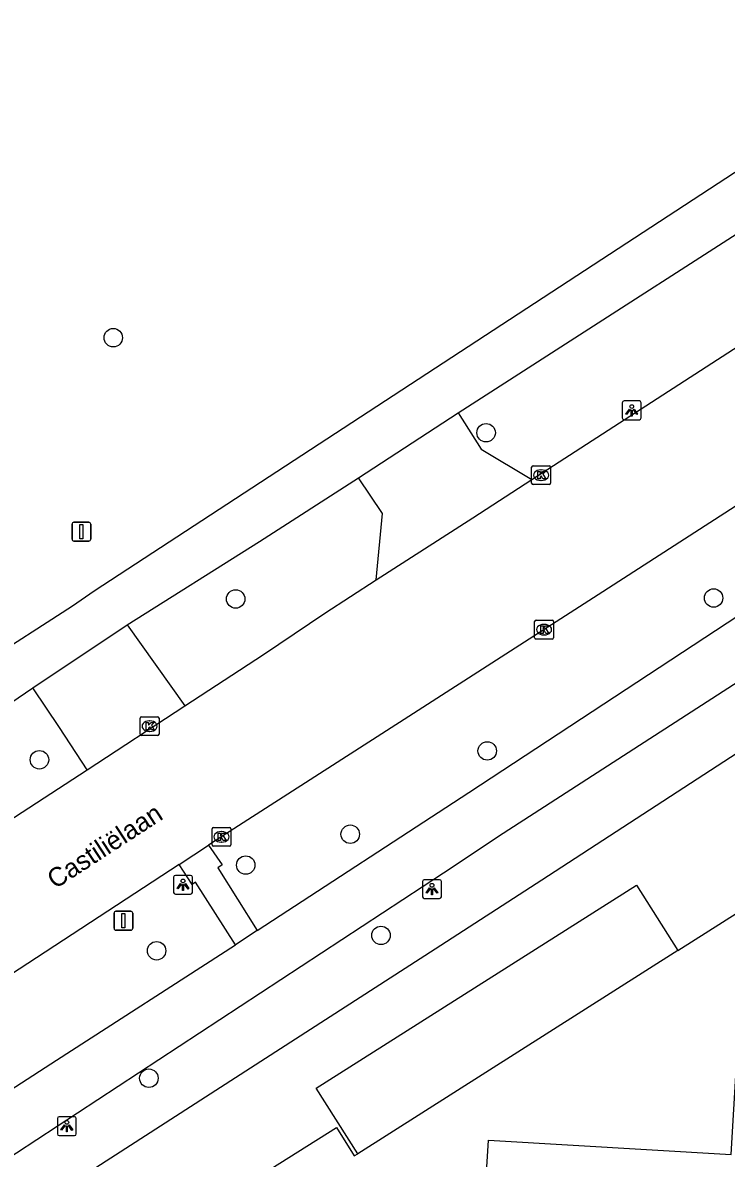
# Model space of a CAD drawing. Extents: x 159451 to 160663, y 388402 to 389723.
# Drawn here: x 159714 to 159751.3, y 389147.8 to 389208 of the extents above; entities that cross this region are included whole.
import ezdxf

# ---------------------------------------------------------------- set-up
doc = ezdxf.new("R2010")
doc.units = 0
for name, color, linetype in [('IMGEO_Boom', 7, 'Continuous'), ('IMGEO_Erf', 7, 'Continuous'), ('IMGEO_Fietspad_gesloten', 7, 'Continuous'), ('IMGEO_Kolk', 7, 'Continuous'), ('IMGEO_Lichtpunt', 7, 'Continuous'), ('IMGEO_Openbare_ruimte_label', 7, 'Continuous'), ('IMGEO_Pand', 7, 'Continuous'), ('IMGEO_Rijbaan_lokaal_gesloten', 7, 'Continuous'), ('IMGEO_Rijbaan_lokaal_open', 7, 'Continuous'), ('IMGEO_Verkeersbordpaal', 7, 'Continuous'), ('IMGEO_Voetpad_open', 7, 'Continuous')]:
    doc.layers.add(name, color=color, linetype=linetype)

msp = doc.modelspace()

# ---------------------------------------------------------------- linework, layer by layer
at = {"layer": 'IMGEO_Boom'}
for centre in [(159718.826, 389191.343), (159738.577, 389186.302), (159725.311, 389177.491), (159750.626, 389177.542), (159738.634, 389169.436), (159714.918, 389168.964), (159731.379, 389165.02), (159725.845, 389163.382), (159733.007, 389159.655), (159721.121, 389158.839), (159720.712, 389152.084)]:
    msp.add_circle(centre, 0.489, dxfattribs=at)
at = {"layer": 'IMGEO_Erf'}
for points in [[(159748.739, 389158.847), (159759.109, 389165.438), (159760.359, 389163.401)], [(159722.516, 389095.413), (159722.792, 389100.259), (159711.104, 389100.923), (159702.284, 389112.933), (159706.835, 389116.275), (159698.631, 389129.303), (159730.65, 389149.467), (159731.596, 389147.964), (159731.782, 389148.082)]]:
    msp.add_lwpolyline(points, dxfattribs=at)
at = {"layer": 'IMGEO_Fietspad_gesloten'}
for points in [[(159696.145, 389164.01), (159699.251, 389166.039), (159708.794, 389172.235), (159708.905, 389172.147), (159709.019, 389172.233), (159711.829, 389174.024), (159716.666, 389177.127), (159717.814, 389177.926), (159784.328, 389221.435)], [(159737.096, 389187.355), (159758.299, 389200.996), (159781.643, 389216.263)], [(159726.442, 389159.917), (159737.666, 389167.226), (159753.709, 389177.779), (159791.193, 389202.242)], [(159689.337, 389132.758), (159694.349, 389135.637), (159709.37, 389145.295), (159736.324, 389162.971), (159739.475, 389165.082), (159753.328, 389174.015), (159770.977, 389185.573), (159792.742, 389199.315)], [(159719.558, 389176.127), (159726.565, 389180.529), (159731.823, 389183.917)], [(159677.543, 389148.933), (159683.696, 389152.464), (159687.097, 389154.672), (159691.96, 389158.015), (159702.684, 389165.018), (159709.597, 389169.401), (159714.574, 389172.778)], [(159726.442, 389159.917), (159725.301, 389159.156)], [(159686.936, 389134.846), (159692.451, 389138.046), (159696.672, 389140.641), (159715.829, 389153.048), (159725.301, 389159.156)]]:
    msp.add_lwpolyline(points, dxfattribs=at)
at = {"layer": 'IMGEO_Kolk'}
for p, q in [((159740.988, 389183.631), (159740.988, 389184.483)), ((159741.063, 389184.557), (159741.915, 389184.557)), ((159741.476, 389184.337), (159741.501, 389184.337)), ((159741.989, 389184.483), (159741.989, 389183.631)), ((159741.499, 389183.777), (159741.474, 389183.777)), ((159741.915, 389183.557), (159741.063, 389183.557)), ((159741.146, 389175.439), (159741.146, 389176.291)), ((159741.221, 389176.365), (159742.073, 389176.365)), ((159741.634, 389176.145), (159741.659, 389176.145)), ((159742.147, 389176.291), (159742.147, 389175.439)), ((159742.073, 389175.365), (159741.221, 389175.365)), ((159741.657, 389175.585), (159741.632, 389175.585)), ((159720.253, 389170.323), (159720.253, 389171.175)), ((159720.328, 389171.249), (159721.18, 389171.249)), ((159720.741, 389171.029), (159720.766, 389171.029)), ((159721.254, 389171.175), (159721.254, 389170.323)), ((159720.764, 389170.469), (159720.739, 389170.469)), ((159721.18, 389170.249), (159720.328, 389170.249)), ((159724.061, 389164.451), (159724.061, 389165.303)), ((159724.136, 389165.377), (159724.988, 389165.377)), ((159724.549, 389165.157), (159724.574, 389165.157)), ((159725.062, 389165.303), (159725.062, 389164.451)), ((159724.988, 389164.377), (159724.136, 389164.377)), ((159724.572, 389164.597), (159724.547, 389164.597))]:
    msp.add_line(p, q, dxfattribs=at)
for points in [[(159740.988, 389183.631), (159740.988, 389184.483)], [(159741.063, 389184.557), (159741.915, 389184.557)], [(159741.309, 389184.257), (159741.432, 389184.257), (159741.432, 389184.106), (159741.562, 389184.257), (159741.726, 389184.257), (159741.58, 389184.106), (159741.733, 389183.857), (159741.581, 389183.857), (159741.496, 389184.021), (159741.432, 389183.954), (159741.432, 389183.857), (159741.309, 389183.857), (159741.309, 389184.257)], [(159741.989, 389184.483), (159741.989, 389183.631)], [(159741.915, 389183.557), (159741.063, 389183.557)], [(159741.146, 389175.439), (159741.146, 389176.291)], [(159741.221, 389176.365), (159742.073, 389176.365)], [(159741.467, 389176.065), (159741.59, 389176.065), (159741.59, 389175.914), (159741.72, 389176.065), (159741.884, 389176.065), (159741.738, 389175.914), (159741.891, 389175.665), (159741.739, 389175.665), (159741.654, 389175.829), (159741.59, 389175.762), (159741.59, 389175.665), (159741.467, 389175.665), (159741.467, 389176.065)], [(159742.147, 389176.291), (159742.147, 389175.439)], [(159742.073, 389175.365), (159741.221, 389175.365)], [(159720.253, 389170.323), (159720.253, 389171.175)], [(159720.328, 389171.249), (159721.18, 389171.249)], [(159721.254, 389171.175), (159721.254, 389170.323)], [(159720.574, 389170.949), (159720.697, 389170.949), (159720.697, 389170.798), (159720.827, 389170.949), (159720.991, 389170.949), (159720.845, 389170.798), (159720.998, 389170.549), (159720.846, 389170.549), (159720.761, 389170.713), (159720.697, 389170.646), (159720.697, 389170.549), (159720.574, 389170.549), (159720.574, 389170.949)], [(159721.18, 389170.249), (159720.328, 389170.249)], [(159724.061, 389164.451), (159724.061, 389165.303)], [(159724.136, 389165.377), (159724.988, 389165.377)], [(159724.382, 389165.077), (159724.505, 389165.077), (159724.505, 389164.926), (159724.635, 389165.077), (159724.799, 389165.077), (159724.653, 389164.926), (159724.806, 389164.677), (159724.654, 389164.677), (159724.569, 389164.841), (159724.505, 389164.774), (159724.505, 389164.677), (159724.382, 389164.677), (159724.382, 389165.077)], [(159725.062, 389165.303), (159725.062, 389164.451)], [(159724.988, 389164.377), (159724.136, 389164.377)]]:
    msp.add_lwpolyline(points, dxfattribs=at)
for centre, start, end in [((159741.065, 389184.481), 91.55205, 178.44795), ((159741.065, 389184.481), 91.55205, 178.44795), ((159741.913, 389184.481), 1.55205, 88.44795), ((159741.913, 389184.481), 1.55205, 88.44795), ((159741.065, 389183.633), 181.55205, 268.44795), ((159741.065, 389183.633), 181.55205, 268.44795), ((159741.913, 389183.633), 271.55205, 358.44795), ((159741.913, 389183.633), 271.55205, 358.44795), ((159741.223, 389176.289), 91.55205, 178.44795), ((159741.223, 389176.289), 91.55205, 178.44795), ((159742.071, 389176.289), 1.55205, 88.44795), ((159742.071, 389176.289), 1.55205, 88.44795), ((159741.223, 389175.441), 181.55205, 268.44795), ((159741.223, 389175.441), 181.55205, 268.44795), ((159742.071, 389175.441), 271.55205, 358.44795), ((159742.071, 389175.441), 271.55205, 358.44795), ((159720.33, 389171.173), 91.55205, 178.44795), ((159720.33, 389171.173), 91.55205, 178.44795), ((159721.178, 389171.173), 1.55205, 88.44795), ((159721.178, 389171.173), 1.55205, 88.44795), ((159720.33, 389170.325), 181.55205, 268.44795), ((159720.33, 389170.325), 181.55205, 268.44795), ((159721.178, 389170.325), 271.55205, 358.44795), ((159721.178, 389170.325), 271.55205, 358.44795), ((159724.138, 389165.301), 91.55205, 178.44795), ((159724.138, 389165.301), 91.55205, 178.44795), ((159724.986, 389165.301), 1.55205, 88.44795), ((159724.986, 389165.301), 1.55205, 88.44795), ((159724.138, 389164.453), 181.55205, 268.44795), ((159724.138, 389164.453), 181.55205, 268.44795), ((159724.986, 389164.453), 271.55205, 358.44795), ((159724.986, 389164.453), 271.55205, 358.44795)]:
    msp.add_arc(centre, 0.0765, start, end, dxfattribs=at)
for centre, major_axis, ratio, start_param, end_param in [((159741.475, 389184.057), (-0.387, 0.002), 0.722429, 4.712389, 7.853982), ((159741.5, 389184.057), (-0.39, 0.002), 0.717154, 1.570796, 4.712389), ((159741.633, 389175.865), (-0.387, 0.002), 0.722429, 4.712389, 7.853982), ((159741.658, 389175.865), (-0.39, 0.002), 0.717154, 1.570796, 4.712389), ((159720.74, 389170.749), (-0.387, 0.002), 0.722429, 4.712389, 7.853982), ((159720.765, 389170.749), (-0.39, 0.002), 0.717154, 1.570796, 4.712389), ((159724.548, 389164.877), (-0.387, 0.002), 0.722429, 4.712389, 7.853982), ((159724.573, 389164.877), (-0.39, 0.002), 0.717154, 1.570796, 4.712389)]:
    msp.add_ellipse(centre, major_axis=major_axis, ratio=ratio, start_param=start_param, end_param=end_param, dxfattribs=at)
at = {"layer": 'IMGEO_Lichtpunt'}
for p, q in [((159745.791, 389187.893), (159745.791, 389187.086)), ((159745.791, 389187.893), (159745.791, 389187.086)), ((159746.693, 389187.988), (159745.885, 389187.988)), ((159746.693, 389187.988), (159745.885, 389187.988)), ((159746.787, 389187.086), (159746.787, 389187.893)), ((159746.787, 389187.086), (159746.787, 389187.893)), ((159745.885, 389186.992), (159746.693, 389186.992)), ((159745.885, 389186.992), (159746.693, 389186.992)), ((159722.022, 389162.741), (159722.022, 389161.934)), ((159722.022, 389162.741), (159722.022, 389161.934)), ((159722.924, 389162.836), (159722.116, 389162.836)), ((159722.924, 389162.836), (159722.116, 389162.836)), ((159723.018, 389161.934), (159723.018, 389162.741)), ((159723.018, 389161.934), (159723.018, 389162.741)), ((159736.111, 389162.607), (159735.303, 389162.607)), ((159736.111, 389162.607), (159735.303, 389162.607)), ((159735.209, 389162.512), (159735.209, 389161.705)), ((159735.209, 389162.512), (159735.209, 389161.705)), ((159736.205, 389161.705), (159736.205, 389162.512)), ((159736.205, 389161.705), (159736.205, 389162.512)), ((159722.116, 389161.84), (159722.924, 389161.84)), ((159722.116, 389161.84), (159722.924, 389161.84)), ((159735.303, 389161.611), (159736.111, 389161.611)), ((159735.303, 389161.611), (159736.111, 389161.611)), ((159715.869, 389149.946), (159715.869, 389149.139)), ((159715.869, 389149.946), (159715.869, 389149.139)), ((159716.771, 389150.041), (159715.963, 389150.041)), ((159716.771, 389150.041), (159715.963, 389150.041)), ((159716.865, 389149.139), (159716.865, 389149.946)), ((159716.865, 389149.139), (159716.865, 389149.946)), ((159715.963, 389149.045), (159716.771, 389149.045)), ((159715.963, 389149.045), (159716.771, 389149.045))]:
    msp.add_line(p, q, dxfattribs=at)
for points in [[(159746.165, 389187.557), (159746.204, 389187.529), (159746.016, 389187.267), (159745.978, 389187.294), (159746.165, 389187.557)], [(159746.267, 389187.509), (159746.314, 389187.509), (159746.314, 389187.187), (159746.267, 389187.187), (159746.267, 389187.509)], [(159746.377, 389187.529), (159746.415, 389187.556), (159746.602, 389187.294), (159746.563, 389187.266), (159746.377, 389187.529)], [(159722.396, 389162.405), (159722.435, 389162.377), (159722.247, 389162.115), (159722.209, 389162.142), (159722.396, 389162.405)], [(159722.498, 389162.357), (159722.545, 389162.357), (159722.545, 389162.035), (159722.498, 389162.035), (159722.498, 389162.357)], [(159722.608, 389162.377), (159722.646, 389162.404), (159722.833, 389162.142), (159722.794, 389162.114), (159722.608, 389162.377)], [(159735.583, 389162.176), (159735.622, 389162.148), (159735.434, 389161.886), (159735.396, 389161.913), (159735.583, 389162.176)], [(159735.685, 389162.128), (159735.732, 389162.128), (159735.732, 389161.806), (159735.685, 389161.806), (159735.685, 389162.128)], [(159735.795, 389162.148), (159735.833, 389162.175), (159736.02, 389161.913), (159735.981, 389161.885), (159735.795, 389162.148)], [(159716.243, 389149.61), (159716.282, 389149.582), (159716.094, 389149.32), (159716.056, 389149.347), (159716.243, 389149.61)], [(159716.345, 389149.562), (159716.392, 389149.562), (159716.392, 389149.24), (159716.345, 389149.24), (159716.345, 389149.562)], [(159716.455, 389149.582), (159716.493, 389149.609), (159716.68, 389149.347), (159716.641, 389149.319), (159716.455, 389149.582)]]:
    msp.add_lwpolyline(points, dxfattribs=at)
for centre in [(159746.29, 389187.691), (159722.521, 389162.539), (159735.708, 389162.31), (159716.368, 389149.744)]:
    msp.add_circle(centre, 0.0994, dxfattribs=at)
for centre, start, end in [((159745.885, 389187.893), 90, 180), ((159745.885, 389187.893), 90, 180), ((159746.693, 389187.893), 0, 90), ((159746.693, 389187.893), 0, 90), ((159745.885, 389187.086), 180, 270), ((159745.885, 389187.086), 180, 270), ((159746.693, 389187.086), 270, 0), ((159746.693, 389187.086), 270, 360), ((159722.116, 389162.741), 90, 180), ((159722.116, 389162.741), 90, 180), ((159722.924, 389162.741), 0, 90), ((159722.924, 389162.741), 0, 90), ((159735.303, 389162.512), 90, 180), ((159735.303, 389162.512), 90, 180), ((159736.111, 389162.512), 0, 90), ((159736.111, 389162.512), 0, 90), ((159722.116, 389161.934), 180, 270), ((159722.116, 389161.934), 180, 270), ((159722.924, 389161.934), 270, 0), ((159722.924, 389161.934), 270, 360), ((159735.303, 389161.705), 180, 270), ((159735.303, 389161.705), 180, 270), ((159736.111, 389161.705), 270, 0), ((159736.111, 389161.705), 270, 360), ((159715.963, 389149.946), 90, 180), ((159715.963, 389149.946), 90, 180), ((159716.771, 389149.946), 0, 90), ((159716.771, 389149.946), 0, 90), ((159715.963, 389149.139), 180, 270), ((159715.963, 389149.139), 180, 270), ((159716.771, 389149.139), 270, 0), ((159716.771, 389149.139), 270, 360)]:
    msp.add_arc(centre, 0.0946, start, end, dxfattribs=at)
at = {"layer": 'IMGEO_Pand'}
for points in [[(159738.622, 389147.373), (159738.705, 389148.792), (159751.564, 389148.043), (159751.843, 389152.835), (159759.116, 389152.411), (159757.938, 389134.296), (159765.449, 389133.857), (159765.609, 389136.592), (159763.423, 389136.72), (159763.861, 389144.223), (159777.397, 389143.433), (159777.143, 389139.066), (159779.789, 389138.912), (159783.307, 389142.042), (159781.229, 389144.377), (159796.232, 389157.731), (159796.629, 389157.236), (159798.314, 389158.735), (159797.96, 389159.134), (159803.071, 389163.682)], [(159731.782, 389148.082), (159729.582, 389151.548), (159746.539, 389162.313), (159748.739, 389158.847)], [(159748.739, 389158.847), (159731.782, 389148.082)]]:
    msp.add_lwpolyline(points, dxfattribs=at)
at = {"layer": 'IMGEO_Rijbaan_lokaal_gesloten'}
for points in [[(159741.003, 389183.824), (159754.281, 389192.419), (159786.052, 389212.871), (159787.24, 389213.635)], [(159789.616, 389206.936), (159771.403, 389195.071), (159744.513, 389177.711), (159734.489, 389171.264), (159724.275, 389164.695), (159723.871, 389164.431)], [(159732.761, 389178.498), (159737.877, 389181.8), (159741.003, 389183.824)], [(159722.626, 389171.817), (159726.781, 389174.542), (159730.042, 389176.743), (159732.761, 389178.498)], [(159717.44, 389168.436), (159722.626, 389171.817)], [(159693.85, 389153.343), (159702.485, 389158.94), (159712.067, 389164.934), (159717.44, 389168.436)], [(159722.322, 389163.419), (159723.871, 389164.431)], [(159722.322, 389163.419), (159706.263, 389152.922), (159697.619, 389147.345)]]:
    msp.add_lwpolyline(points, dxfattribs=at)
at = {"layer": 'IMGEO_Rijbaan_lokaal_open'}
for points in [[(159731.823, 389183.917), (159737.096, 389187.355)], [(159737.096, 389187.355), (159738.318, 389185.435), (159741.003, 389183.824)], [(159732.761, 389178.498), (159733.084, 389182.02), (159731.823, 389183.917)], [(159714.574, 389172.778), (159719.558, 389176.127)], [(159719.558, 389176.127), (159722.626, 389171.817)], [(159717.44, 389168.436), (159715.973, 389170.679), (159714.574, 389172.778)]]:
    msp.add_lwpolyline(points, dxfattribs=at)
at = {"layer": 'IMGEO_Verkeersbordpaal'}
for p, q in [((159716.642, 389180.657), (159716.642, 389181.457)), ((159716.642, 389181.457), (159716.642, 389180.657)), ((159716.742, 389181.557), (159717.532, 389181.557)), ((159717.532, 389181.557), (159716.742, 389181.557)), ((159717.632, 389181.457), (159717.632, 389180.657)), ((159717.632, 389180.657), (159717.632, 389181.457)), ((159717.532, 389180.557), (159716.742, 389180.557)), ((159716.742, 389180.557), (159717.532, 389180.557)), ((159718.87, 389160.032), (159718.87, 389160.832)), ((159718.87, 389160.832), (159718.87, 389160.032)), ((159718.97, 389160.932), (159719.76, 389160.932)), ((159719.76, 389160.932), (159718.97, 389160.932)), ((159719.86, 389160.832), (159719.86, 389160.032)), ((159719.86, 389160.032), (159719.86, 389160.832)), ((159719.76, 389159.932), (159718.97, 389159.932)), ((159718.97, 389159.932), (159719.76, 389159.932))]:
    msp.add_line(p, q, dxfattribs=at)
for points in [[(159717.062, 389181.432), (159717.212, 389181.432), (159717.212, 389180.682), (159717.062, 389180.682), (159717.062, 389181.432)], [(159719.29, 389160.807), (159719.44, 389160.807), (159719.44, 389160.057), (159719.29, 389160.057), (159719.29, 389160.807)]]:
    msp.add_lwpolyline(points, dxfattribs=at)
for centre, start, end in [((159716.742, 389181.457), 90, 180), ((159716.742, 389181.457), 90, 180), ((159717.532, 389181.457), 0, 90), ((159717.532, 389181.457), 360, 90), ((159716.742, 389180.657), 180, 270), ((159716.742, 389180.657), 180, 270), ((159717.532, 389180.657), 270, 0), ((159717.532, 389180.657), 270, 0), ((159718.97, 389160.832), 90, 180), ((159718.97, 389160.832), 90, 180), ((159719.76, 389160.832), 0, 90), ((159719.76, 389160.832), 360, 90), ((159718.97, 389160.032), 180, 270), ((159718.97, 389160.032), 180, 270), ((159719.76, 389160.032), 270, 0), ((159719.76, 389160.032), 270, 0)]:
    msp.add_arc(centre, 0.1, start, end, dxfattribs=at)
at = {"layer": 'IMGEO_Voetpad_open'}
for points in [[(159795.244, 389197.332), (159777.608, 389186.061), (159741.53, 389162.589), (159735.885, 389158.916), (159701.744, 389136.928), (159687.597, 389128.372)], [(159723.871, 389164.431), (159724.588, 389163.392), (159724.374, 389163.237), (159726.442, 389159.917)], [(159725.301, 389159.156), (159723.188, 389162.468), (159723.009, 389162.351), (159722.322, 389163.419)]]:
    msp.add_lwpolyline(points, dxfattribs=at)

# ---------------------------------------------------------------- texts
at = {"layer": 'IMGEO_Openbare_ruimte_label'}
msp.add_text('Castiliëlaan', height=1, rotation=33.08631, dxfattribs=at).set_placement((159715.746, 389162.088))

doc.saveas('drawing.dxf')
